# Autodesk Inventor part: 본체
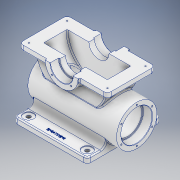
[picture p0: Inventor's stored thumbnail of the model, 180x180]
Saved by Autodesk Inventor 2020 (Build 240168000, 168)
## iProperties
Created: 2023-07
Part Number: 본체
Material: 알루미늄 6061
Document SubType Name: Modeling
Designer: com
Density: 2.7 g/cm^3
Appearance: 알루미늄 - 평지
Author: com
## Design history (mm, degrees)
sketch "스케치2"
  geometry: L1 (55, 121)-(0, 121); L2 (0, 121)-(0, -121); L3 (0, -121)-(55, -121); L4 (55, -121)-(55, 121); L5 (42.5, 121)-(42.5, 96); L6 (42.5, 96)-(38.5, 96); L7 (38.5, 96)-(38.5, -96); L8 (38.5, -96)-(42.5, -96); L9 (42.5, -96)-(42.5, -121); 2 further points
  constraints: 18 end point, 5 perpendicular, 2 parallel, 2 point on line, 1 coincident, 1 horizontal, 1 midpoint, 1 vertical
  dimensions: "d0" = 110 diameter of L4 L2; "d1" = 242 distance of L3.end L1.start; "d2" = 77 diameter of L7 L2; "d3" = 85 diameter of L5 L2; "d4" = 85 diameter of L9 L2; "d5" = 25 distance of L5.start L5.end; "d6" = 25 distance of L8.end L9.end
revolve "회전1" stored, may be unused: angle "d13" = 90 deg
sketch "스케치3"
  geometry: L1 (100, 134)-(85, 134); L2 (85, 134)-(85, -106); L3 (85, -106)-(100, -106); L4 (100, -106)-(100, 134); L5 (-55, 121)-(-55, -121) reference; L6 (-45, 114)-(-60, 114); L7 (-60, 114)-(-60, -86); L8 (-60, -86)-(-45, -86); L9 (-45, -86)-(-45, 114); C1 r 45 at (100, 14); A1 r 87 centre (100, 14) between (100, 101) and (100, -73); A2 r 100 centre (100, 14) between (100, 114) and (100, -86); 7 further points
  constraints: 16 end point, 4 parallel, 4 point on circle, 4 point on line, 3 centre point, 2 coincident, 2 horizontal, 2 perpendicular, 1 midpoint
  dimensions: "d14" = 15 distance of L2.end L3.end; "d16" = 240 distance of L3.end L1.start; "d17" = 87 radius of A1; "d18" = 100 radius of A2; "d19" = 107 vertical distance of A1.centre L5.start; "d20" = 90 diameter of C1; "d28" = 60 distance from line of L7 point (0, 0); "d29" = 15 distance of L7.end L8.end; "d31" = 200 distance of L6.end L7.end; "d32" = 7 distance from line of L6 L5.start; "d33" = 100 distance from line of A1.centre L6 (derived); "d97" = 160 distance between parallel lines of L7 L4
extrude "돌출1" join sketch "스케치3" stored distance "d21" = 130; taper "d22" = 0 deg
extrude "돌출2" join sketch "스케치3" stored distance "d23" = 90; taper "d24" = 0 deg
extrude "돌출5" join sketch "스케치3" stored distance "d47" = 140; taper "d48" = 0 deg
extrude "돌출3" cut sketch "스케치3" stored distance "d25" = 64; taper "d26" = 0 deg
sketch "스케치5"
  geometry: A1 r 45 centre (-14, 100) between (-59, 100) and (31, 100) reference; 2 further points
  constraints: 1 coincident
hole "구멍2" sketch "스케치5" at (-14, 100) diameter "d49" = 55; stored, may be unused: countersink angle "d53" = 90 deg, drill point angle "d55" = 118 deg; dims "d50" = 8, "d51" = 62, "d52" = 23, "d54" = 11.8
sketch "스케치6"
  geometry: L1 (-14, 100)-(17.82, 68.18); L2 (-14, 100)-(-45.82, 68.18); L3 (-14, 100)-(-14, 55); A1 r 37 centre (-14, 100) between (-40.163, 73.837) and (12.163, 73.837); A2 r 45 centre (-14, 100) between (-59, 100) and (31, 100) reference; A3 r 45 centre (-14, 100) between (-56.426, 85) and (28.426, 85) reference; 1 further point
  constraints: 6 end point, 5 point on circle, 2 point on line, 1 centre point, 1 concentric
  dimensions: "d56" = 74 diameter of A1; "d57" = 45 deg angle of L3 L1; "d58" = 45 deg angle of L3 L2 (= d57)
hole "구멍3" sketch "스케치6" at (-40.163, 73.837), (12.163, 73.837) diameter "d59" = 4.134; stored, may be unused: countersink angle "d63" = 90 deg, drill point angle "d65" = 118 deg; dims "d60" = 10, "d61" = 62, "d62" = 23, "d64" = 12
revolve "회전2" stored, may be unused: angle "d27" = 90 deg
extrude "돌출4" join sketch "스케치3" stored distance "d34" = 200; taper "d35" = 0 deg
fillet "모깎기1" dims "d36" = 15
fillet "모깎기2" dims "d37" = 10
sketch "스케치4"
  geometry: L1 (3, 117)-(217, 117); L2 (217, 117)-(217, 13); L3 (217, 13)-(3, 13); L4 (3, 13)-(3, 117); L5 (-10, 120)-(-10, 10) reference; L6 (79, 135)-(141, 135) reference; 5 further points
  constraints: 8 end point, 4 midpoint, 2 parallel, 1 horizontal, 1 horizontal alignment, 1 perpendicular, 1 vertical alignment
  dimensions: "d38" = 104 distance of L3.end L1.start; "d39" = 214 distance of L1.start L1.end
hole "구멍1" sketch "스케치4" at (3, 117), (3, 13), (217, 117), (217, 13) diameter "d40" = 3.242; stored, may be unused: countersink angle "d44" = 90 deg, drill point angle "d46" = 118 deg; dims "d41" = 8, "d42" = 4, "d43" = 2, "d45" = 11.8
sketch "스케치7"
  geometry: L1 (20, 143.246)-(180, 143.246); L2 (180, 143.246)-(180, -16.754); L3 (180, -16.754)-(20, -16.754); L4 (20, -16.754)-(20, 143.246); L5 (190, 163.246)-(10, 163.246) reference; L6 (0, 112.938)-(0, 13.553) reference; 5 further points
  constraints: 8 end point, 4 midpoint, 2 parallel, 1 horizontal, 1 horizontal alignment, 1 perpendicular, 1 vertical alignment
  dimensions: "d66" = 160 distance of L1.start L1.end; "d67" = 160 distance of L3.end L1.start
hole "구멍4" sketch "스케치7" at (20, -16.754), (180, -16.754), (180, 143.246), (20, 143.246) diameter "d68" = 11; stored, may be unused: countersink angle "d72" = 90 deg, drill point angle "d74" = 118 deg; dims "d69" = 10, "d70" = 28, "d71" = 2, "d73" = 14.2
sketch "스케치8" dims "d75" = 97
  geometry: 3 further points
  constraints: 2 vertical alignment, 1 coincident, 2 other
hole "구멍5" sketch "스케치8" at (0, 48.5) diameter "d76" = 4.134; stored, may be unused: countersink angle "d80" = 90 deg, drill point angle "d82" = 118 deg; dims "d77" = 10, "d78" = 28, "d79" = 2, "d81" = 12
fillet "모깎기3" dims "d86" = 1.1
fillet "모깎기4" dims "d87" = 1
fillet "모깎기5" dims "d88" = 3
chamfer "모따기1" distance "d89" = 1; stored, may be unused: second distance "d90" = 2, angle "d91" = 45 deg
sketch "스케치9"
  geometry: L1 (72, -17.754)-(122, -17.754); L2 (122, -17.754)-(122, -25.754); L3 (122, -25.754)-(72, -25.754); L4 (72, -25.754)-(72, -17.754); L5 (122, -17.754)-(72, -25.754); L6 (72, -17.754)-(122, -25.754); L7 (7, -36.754)-(187, -36.754) reference; 4 further points
  constraints: 4 end point, 3 midpoint, 1 horizontal, 1 vertical alignment, 2 other
  dimensions: "d94" = 15 distance from line of L7 point (97, -21.754)
extrude "돌출6" join sketch "스케치9" distance "d95" = 0.5; taper "d96" = 0 deg
node "솔리드1"
mirror "미러1"
pattern_circular "원형 패턴1" dims angle "d84" = 360 deg
mirror "미러2"
feature "A9D066F2-1C7D-4E18-AEED-F7BC21143FA4" dims "d49" = 55, "d50" = 8, "d51" = 62, "d52" = 23, "d53" = 90 deg, "d54" = 11.8, "d55" = 118 deg
